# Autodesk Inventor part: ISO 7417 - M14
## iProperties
Created: 2009-02
Part Number: ISO 7417 - M14
Material: Steel
Description: Hexagon nuts for structural bolting, style 2, hot-dip galvanized (oversize tapped) - Product grade A - Property class 9
Document SubType Name: Modeling
Standard: ISO 7417
Designer: 904Chiaki
Standard Revision: First edition 1984-11-15
Standards Organization: ISO
Language: en-US
Size Designation: M14
Categories: <MemberInstance><Categories><Category DisplayName="Fasteners" InternalName="e4da775c-781d-43d5-af7c-5136215cf5a6" Mnemonic="FSTN"><Category DisplayName="Nuts" I
Density: 7.85 g/cm^3
Mass: 29.36 g
Surface Area: 19.8016 cm^2
Volume: 3.74013 cm^3
IsCustomPart: 0
Author: 904Chiaki
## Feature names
1. Body [Extrusion]
2. Chamfer1 [Revolution]
3. Thread [Hole]
4. Chamfer2
5. Chamfer3
